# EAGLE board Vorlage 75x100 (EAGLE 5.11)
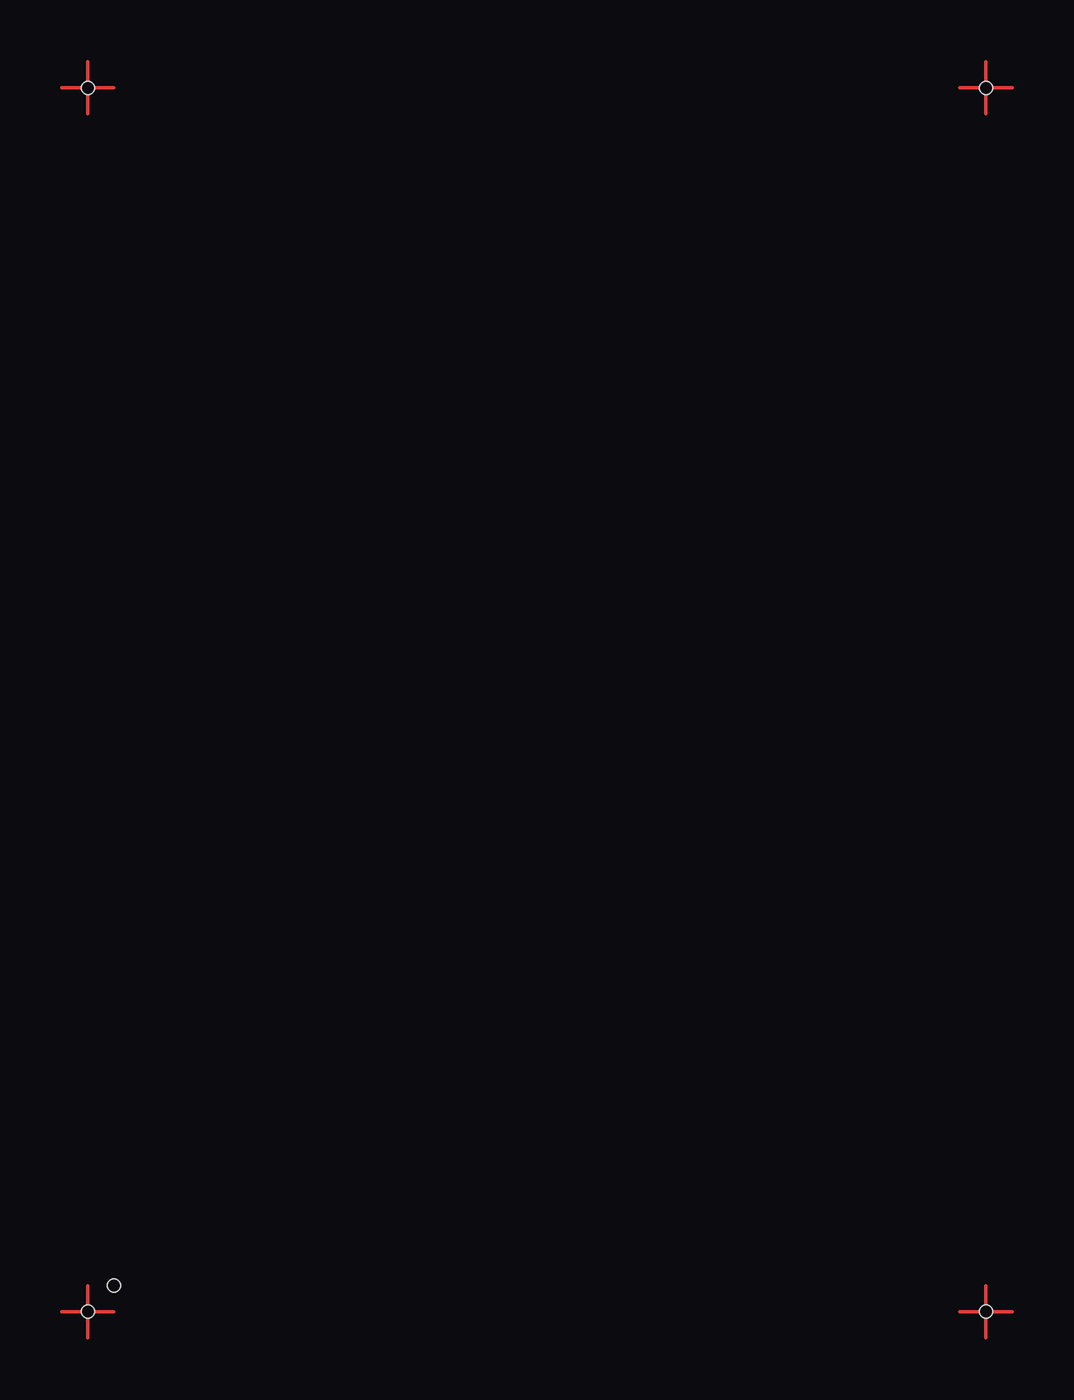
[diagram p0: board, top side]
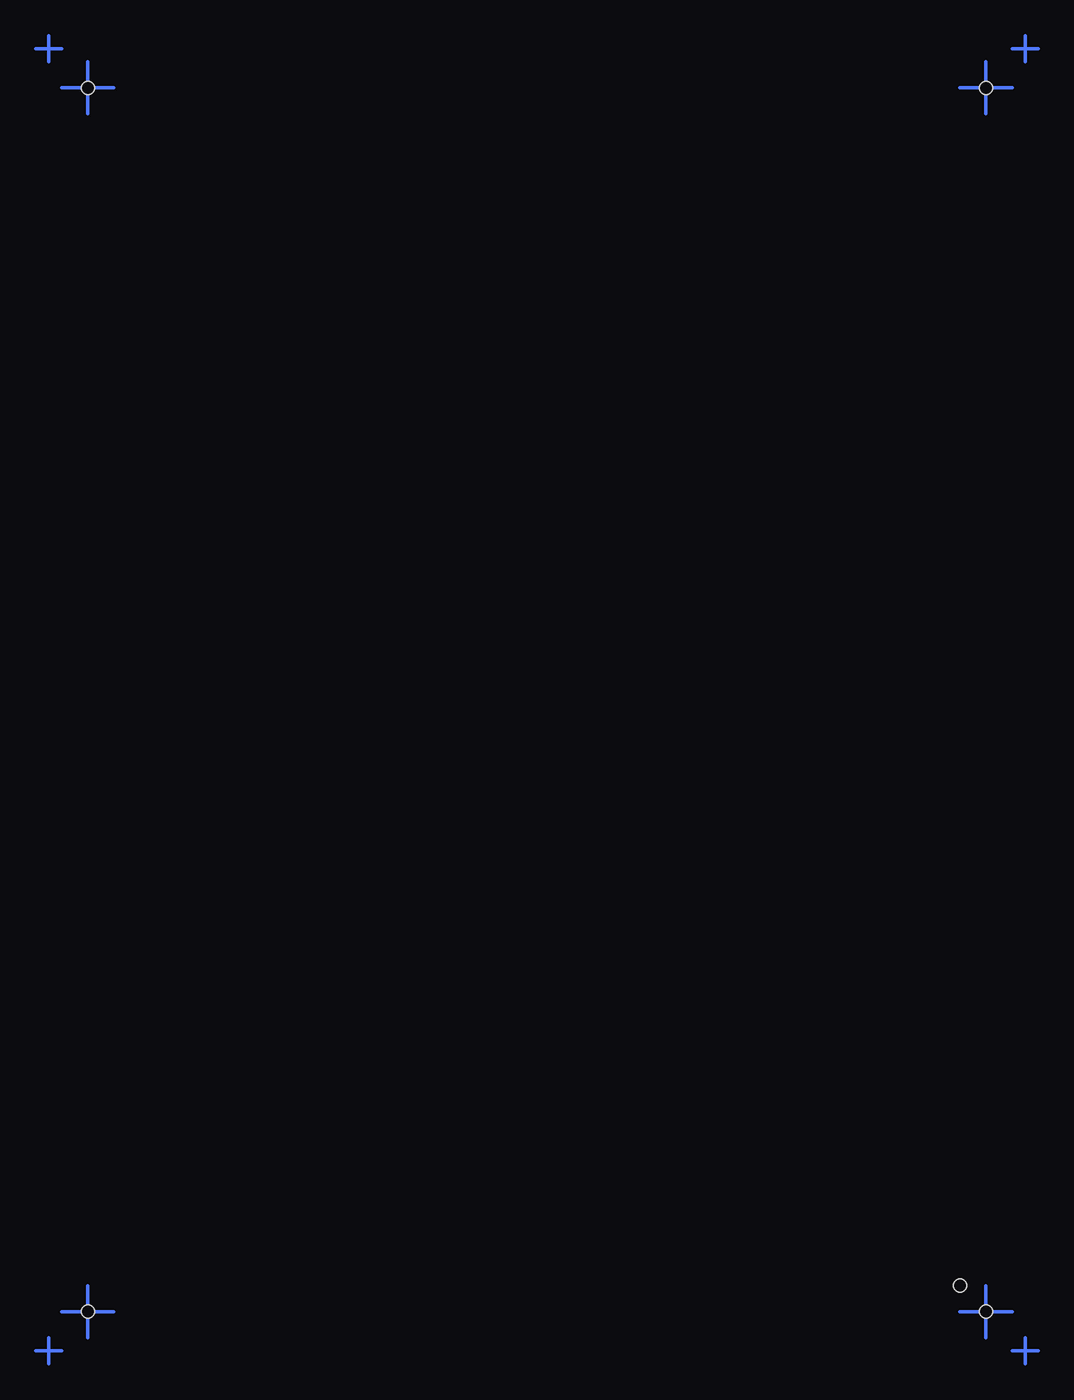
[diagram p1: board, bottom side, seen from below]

No outline drawn. Coordinates in mm, seen from the top.
Copper layers (1*16): Top 0.035mm / dielectric 1.5mm / Bottom 0.035mm
Design rules "default": minimum track width 10mil, minimum drill 24mil, track to track 8mil, track to pad 8mil, pad to pad 8mil, via to via 8mil, smd to smd 8mil, copper to edge 40mil, drill to drill 8mil, minimum pad ring 10mil, minimum via ring 8mil, stop-mask expansion 4mil, vias tented up to drill 0mil, thermal gap 10mil
Holes 1 mm at 3,97 72,97 72,3 3,3 5,5
tKeepout: area 0,0 to 8,8; area 0,92 to 8,100; area 67,92 to 75,100; area 67,0 to 75,8
bKeepout: area 0,92 to 8,100; area 67,92 to 75,100; area 67,0 to 75,8; area 0,0 to 8,8

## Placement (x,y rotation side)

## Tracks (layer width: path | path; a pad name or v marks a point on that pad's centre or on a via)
S$1
  Top 0.254: 1,97 5,97
S$2
  Top 0.254: 3,95 3,99
S$3
  Bottom 0.254: -1,100 1,100
S$4
  Bottom 0.254: 0,99 0,101
S$5
  Bottom 0.254: 1,97 5,97
S$6
  Bottom 0.254: 3,95 3,99
S$7
  Bottom 0.254: 74,100 76,100
S$8
  Bottom 0.254: 75,99 75,101
S$9
  Bottom 0.254: 74,97 70,97
S$10
  Bottom 0.254: 72,95 72,99
S$11
  Top 0.254: 74,97 70,97
S$12
  Top 0.254: 72,95 72,99
S$13
  Top 0.254: 70,3 74,3
S$14
  Top 0.254: 72,1 72,5
S$15
  Bottom 0.254: 70,3 74,3
S$16
  Bottom 0.254: 72,1 72,5
S$17
  Bottom 0.254: 74,0 76,0
S$18
  Bottom 0.254: 75,-1 75,1
S$19
  Bottom 0.254: -1,0 1,0
S$20
  Bottom 0.254: 0,-1 0,1
S$21
  Bottom 0.254: 1,3 5,3
S$22
  Bottom 0.254: 3,1 3,5
S$23
  Top 0.254: 1,3 5,3
S$24
  Top 0.254: 3,1 3,5 3,1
